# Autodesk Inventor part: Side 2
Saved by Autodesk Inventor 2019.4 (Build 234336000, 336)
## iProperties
Created: 2020-06
Part Number: Side 2
Material: Generic
Document SubType Name: Modeling
Designer: Administrator
Density: 1 g/cm^3
Appearance: Default
Title: Side 2
Author: Administrator
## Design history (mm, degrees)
feature "Body1"
body "Solid1"
